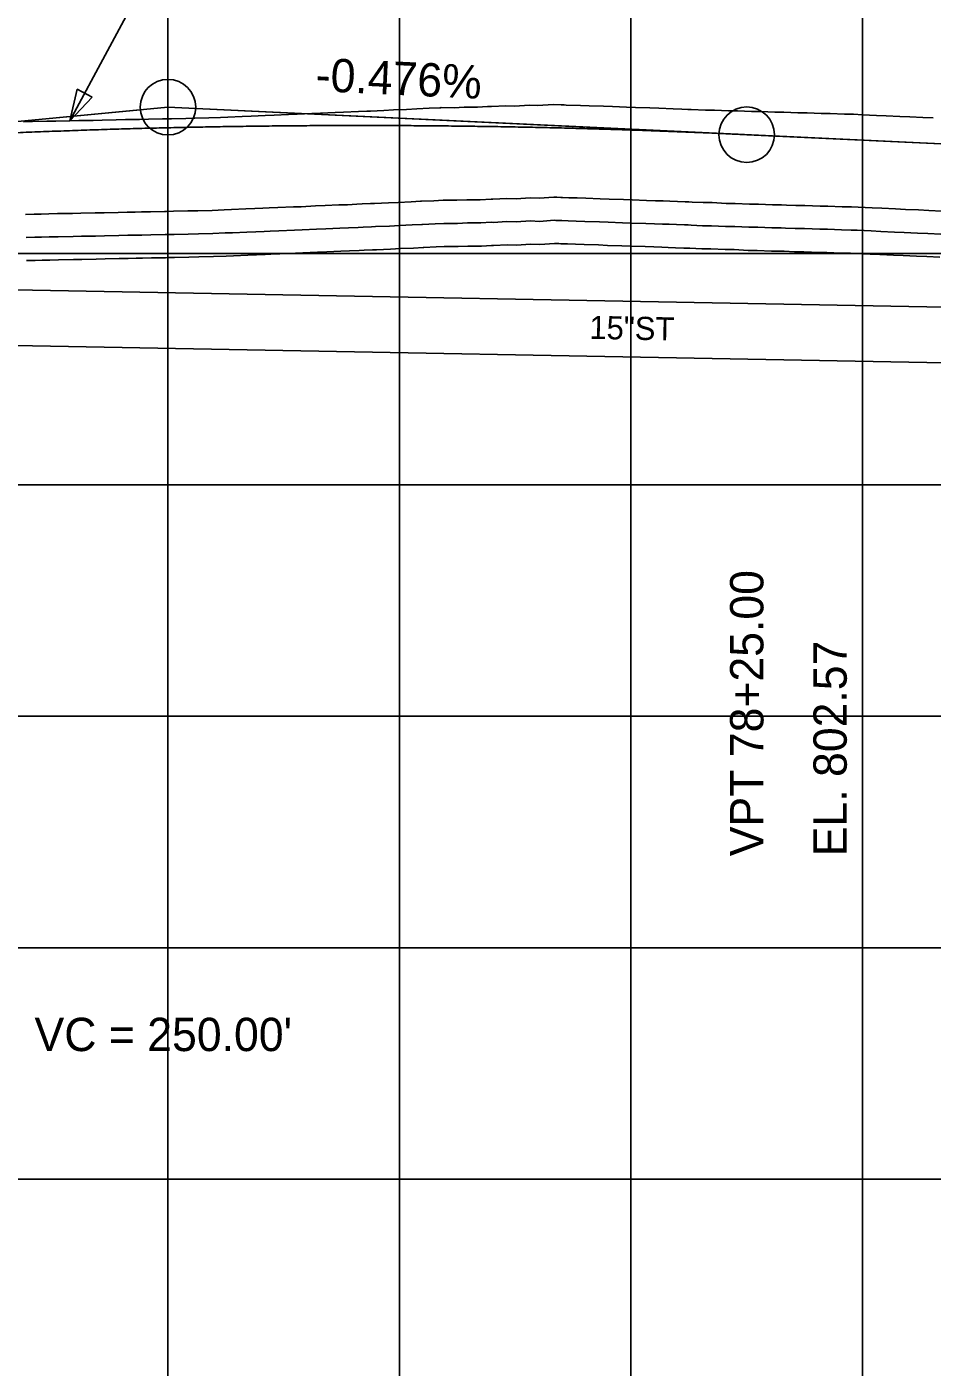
# Model space of a CAD drawing. Extents: x -7164 to 2214450, y -19642 to 253469.
# Drawn here: x 1669.5 to 1865.1, y -1740.6 to -1451 of the extents above; entities that cross this region are included whole.
import ezdxf

# ---------------------------------------------------------------- set-up
doc = ezdxf.new("R2010")
doc.units = 0
for name, color, linetype in [('DESIGN - PROFILE - Proposed', 7, 'Continuous'), ('DESIGN - PROFILE - Proposed Curve Text', 7, 'Continuous'), ('DESIGN - PROFILE - Proposed Text', 7, 'Continuous'), ('DESIGN - SHEET - Light Grid', 7, 'Continuous'), ('SURVEY - PROFILE - Drainage - Storm Sewer', 7, 'Continuous'), ('SURVEY - PROFILE - Drainage - Storm Sewer Text', 7, 'Continuous'), ('SURVEY - PROFILE - Ground Line with Text', 7, 'Continuous'), ('SURVEY - PROFILE - Utilities - Cable with Text', 7, 'Continuous'), ('SURVEY - PROFILE - Utilities - Electric with Text', 7, 'Continuous'), ('XTREE', 7, 'Continuous')]:
    doc.layers.add(name, color=color, linetype=linetype)

msp = doc.modelspace()

# ---------------------------------------------------------------- linework, layer by layer
at = {"layer": 'DESIGN - PROFILE - Proposed'}
msp.add_line((1825, -1474.33), (1885.96, -1477.23), dxfattribs=at)
msp.add_line((1825, -1474.33), (1885.96, -1477.23), dxfattribs=at)
msp.add_spline([(1575, -1480.23), (1580, -1479.77), (1585, -1479.31), (1590, -1478.88), (1595, -1478.45), (1600, -1478.04), (1605, -1477.64), (1610, -1477.26), (1615, -1476.9), (1620, -1476.54), (1625, -1476.2), (1630, -1475.88), (1635, -1475.57), (1640, -1475.27), (1645, -1474.99), (1650, -1474.72), (1655, -1474.47), (1660, -1474.23), (1665, -1474.01), (1670, -1473.79), (1675, -1473.6), (1680, -1473.42), (1685, -1473.25), (1690, -1473.09), (1695, -1472.95), (1700, -1472.83), (1705, -1472.72), (1710, -1472.62), (1715, -1472.54), (1720, -1472.47), (1725, -1472.42), (1730, -1472.38), (1735, -1472.35), (1740, -1472.34), (1745, -1472.34), (1750, -1472.36), (1755, -1472.39), (1760, -1472.44), (1765, -1472.5), (1770, -1472.57), (1775, -1472.66), (1780, -1472.76), (1785, -1472.88), (1790, -1473.01), (1795, -1473.16), (1800, -1473.32), (1805, -1473.49), (1810, -1473.68), (1815, -1473.88), (1820, -1474.1), (1825, -1474.33)], degree=3, dxfattribs=at)
msp.add_spline([(1575, -1480.23), (1580, -1479.77), (1585, -1479.31), (1590, -1478.88), (1595, -1478.45), (1600, -1478.04), (1605, -1477.64), (1610, -1477.26), (1615, -1476.9), (1620, -1476.54), (1625, -1476.2), (1630, -1475.88), (1635, -1475.57), (1640, -1475.27), (1645, -1474.99), (1650, -1474.72), (1655, -1474.47), (1660, -1474.23), (1665, -1474.01), (1670, -1473.79), (1675, -1473.6), (1680, -1473.42), (1685, -1473.25), (1690, -1473.09), (1695, -1472.95), (1700, -1472.83), (1705, -1472.72), (1710, -1472.62), (1715, -1472.54), (1720, -1472.47), (1725, -1472.42), (1730, -1472.38), (1735, -1472.35), (1740, -1472.34), (1745, -1472.34), (1750, -1472.36), (1755, -1472.39), (1760, -1472.44), (1765, -1472.5), (1770, -1472.57), (1775, -1472.66), (1780, -1472.76), (1785, -1472.88), (1790, -1473.01), (1795, -1473.16), (1800, -1473.32), (1805, -1473.49), (1810, -1473.68), (1815, -1473.88), (1820, -1474.1), (1825, -1474.33)], degree=3, dxfattribs=at)
at = {"layer": 'DESIGN - PROFILE - Proposed Text'}
for p, q in [((1575, -1480.23), (1694.03, -1468.94)), ((1575, -1480.23), (1694.03, -1468.94)), ((1825, -1474.33), (1705.99, -1468.66)), ((1825, -1474.33), (1705.99, -1468.66))]:
    msp.add_line(p, q, dxfattribs=at)
msp.add_lwpolyline([(1712.38, -1425.88), (1703.2, -1425.88), (1678.83, -1471.33)], dxfattribs=at)
msp.add_lwpolyline([(1712.38, -1425.88), (1703.2, -1425.88), (1678.83, -1471.33)], dxfattribs=at)
msp.add_lwpolyline([(1683.62, -1466.23), (1678.83, -1471.33), (1680.43, -1464.52)], close=True, dxfattribs=at)
msp.add_lwpolyline([(1683.62, -1466.23), (1678.83, -1471.33), (1680.43, -1464.52)], close=True, dxfattribs=at)
for centre in [(1700, -1468.38), (1700, -1468.38), (1825, -1474.33), (1825, -1474.33)]:
    msp.add_circle(centre, 6, dxfattribs=at)
at = {"layer": 'DESIGN - SHEET - Light Grid'}
for p, q in [((1700, -3000), (1700, -1000)), ((1700, -3000), (1700, -1000)), ((1750, -3000), (1750, -1000)), ((1750, -3000), (1750, -1000)), ((1800, -3000), (1800, -1000)), ((1800, -3000), (1800, -1000)), ((1850, -3000), (1850, -1000)), ((1850, -3000), (1850, -1000)), ((0, -1500), (12400, -1500)), ((0, -1500), (12400, -1500)), ((0, -1550), (12400, -1550)), ((0, -1550), (12400, -1550)), ((0, -1600), (12400, -1600)), ((0, -1600), (12400, -1600)), ((0, -1650), (12400, -1650)), ((0, -1650), (12400, -1650)), ((0, -1700), (12400, -1700)), ((0, -1700), (12400, -1700))]:
    msp.add_line(p, q, dxfattribs=at)
at = {"layer": 'SURVEY - PROFILE - Drainage - Storm Sewer'}
for p, q in [((1504.24, -1504.8), (2097.49, -1515.9)), ((1504.24, -1504.8), (2097.49, -1515.9)), ((1504.24, -1516.8), (2097.49, -1527.9)), ((1504.24, -1516.8), (2097.49, -1527.9))]:
    msp.add_line(p, q, dxfattribs=at)
at = {"layer": 'SURVEY - PROFILE - Ground Line with Text'}
for points in [[(1668.83, -1471.54), (1670.74, -1471.5), (1673.83, -1471.44), (1675.77, -1471.4), (1678.83, -1471.33), (1680.79, -1471.29), (1683.83, -1471.23), (1685.81, -1471.19), (1688.83, -1471.12), (1690.81, -1471.08), (1693.83, -1471.02), (1695.81, -1470.97), (1698.83, -1470.91), (1700.8, -1470.87), (1703.83, -1470.8), (1705.78, -1470.76), (1708.83, -1470.69), (1711.33, -1470.58), (1712.94, -1470.52), (1716.01, -1470.38), (1717.94, -1470.32), (1721.01, -1470.17), (1722.94, -1470.11), (1726.02, -1469.96), (1727.94, -1469.9), (1731.05, -1469.75), (1732.94, -1469.68), (1736.08, -1469.53), (1737.94, -1469.47), (1741.12, -1469.32), (1742.94, -1469.25), (1743.43, -1469.24), (1743.73, -1469.22), (1746.6, -1469.11), (1748.73, -1468.98), (1751.52, -1468.86), (1753.72, -1468.74), (1756.45, -1468.62), (1758.72, -1468.49), (1758.87, -1468.49), (1758.99, -1468.48), (1761.85, -1468.51), (1763.99, -1468.38), (1766.84, -1468.4), (1768.99, -1468.27), (1769.53, -1468.24), (1769.91, -1468.25), (1772.95, -1468.06), (1774.91, -1468.15), (1778.04, -1467.93), (1779.9, -1468.03), (1783.17, -1467.77), (1784.9, -1467.88), (1785.58, -1467.9), (1785.99, -1467.92), (1789.09, -1468.01), (1790.99, -1468.1), (1794.07, -1468.19)], [(1668.83, -1471.54), (1670.74, -1471.5), (1673.83, -1471.44), (1675.77, -1471.4), (1678.83, -1471.33), (1680.79, -1471.29), (1683.83, -1471.23), (1685.81, -1471.19), (1688.83, -1471.12), (1690.81, -1471.08), (1693.83, -1471.02), (1695.81, -1470.97), (1698.83, -1470.91), (1700.8, -1470.87), (1703.83, -1470.8), (1705.78, -1470.76), (1708.83, -1470.69), (1711.33, -1470.58), (1712.94, -1470.52), (1716.01, -1470.38), (1717.94, -1470.32), (1721.01, -1470.17), (1722.94, -1470.11), (1726.02, -1469.96), (1727.94, -1469.9), (1731.05, -1469.75), (1732.94, -1469.68), (1736.08, -1469.53), (1737.94, -1469.47), (1741.12, -1469.32), (1742.94, -1469.25), (1743.43, -1469.24), (1743.73, -1469.22), (1746.6, -1469.11), (1748.73, -1468.98), (1751.52, -1468.86), (1753.72, -1468.74), (1756.45, -1468.62), (1758.72, -1468.49), (1758.87, -1468.49), (1758.99, -1468.48), (1761.85, -1468.51), (1763.99, -1468.38), (1766.84, -1468.4), (1768.99, -1468.27), (1769.53, -1468.24), (1769.91, -1468.25), (1772.95, -1468.06), (1774.91, -1468.15), (1778.04, -1467.93), (1779.9, -1468.03), (1783.17, -1467.77), (1784.9, -1467.88), (1785.58, -1467.9), (1785.99, -1467.92), (1789.09, -1468.01), (1790.99, -1468.1), (1794.07, -1468.19)], [(1794.07, -1468.19), (1795.99, -1468.27), (1799.06, -1468.37), (1800.99, -1468.45), (1804.07, -1468.54), (1805.99, -1468.62), (1809.08, -1468.71), (1810.99, -1468.79), (1812.25, -1468.85), (1813.03, -1468.85), (1816.09, -1469.01), (1818.03, -1469.02), (1821.07, -1469.17), (1823.03, -1469.17), (1826.05, -1469.33), (1828.03, -1469.33), (1831.05, -1469.48), (1833.03, -1469.48), (1836.05, -1469.63), (1838.03, -1469.63), (1841.06, -1469.77), (1843.03, -1469.77), (1846.08, -1469.92), (1848.03, -1469.92), (1850.01, -1470.01), (1853.03, -1470.16), (1855.1, -1470.25), (1858.03, -1470.39), (1860.19, -1470.48), (1863.03, -1470.62), (1865.26, -1470.71)], [(1794.07, -1468.19), (1795.99, -1468.27), (1799.06, -1468.37), (1800.99, -1468.45), (1804.07, -1468.54), (1805.99, -1468.62), (1809.08, -1468.71), (1810.99, -1468.79), (1812.25, -1468.85), (1813.03, -1468.85), (1816.09, -1469.01), (1818.03, -1469.02), (1821.07, -1469.17), (1823.03, -1469.17), (1826.05, -1469.33), (1828.03, -1469.33), (1831.05, -1469.48), (1833.03, -1469.48), (1836.05, -1469.63), (1838.03, -1469.63), (1841.06, -1469.77), (1843.03, -1469.77), (1846.08, -1469.92), (1848.03, -1469.92), (1850.01, -1470.01), (1853.03, -1470.16), (1855.1, -1470.25), (1858.03, -1470.39), (1860.19, -1470.48), (1863.03, -1470.62), (1865.26, -1470.71)]]:
    msp.add_lwpolyline(points, dxfattribs=at)
at = {"layer": 'SURVEY - PROFILE - Utilities - Cable with Text'}
msp.add_lwpolyline([(1669.46, -1501.53), (1671.34, -1501.49), (1672.81, -1501.46), (1674.47, -1501.43), (1676.38, -1501.39), (1679.61, -1501.32), (1681.41, -1501.28), (1684.47, -1501.22), (1686.43, -1501.18), (1689.48, -1501.11), (1691.43, -1501.07), (1693.12, -1501.04), (1694.48, -1501.01), (1696.43, -1500.96), (1699.48, -1500.9), (1699.95, -1500.89), (1701.42, -1500.86), (1704.48, -1500.79), (1706.68, -1500.74), (1709.86, -1500.68), (1712.56, -1500.55), (1714.15, -1500.5), (1717.24, -1500.35), (1719.15, -1500.29), (1720.98, -1500.2), (1722.25, -1500.14), (1724.14, -1500.08), (1727.52, -1499.92), (1729.16, -1499.87), (1732.31, -1499.72), (1734.33, -1499.65), (1737.34, -1499.5), (1739.18, -1499.44), (1741.31, -1499.34), (1742.39, -1499.29), (1744.16, -1499.23), (1745.01, -1499.19), (1748.1, -1499.07), (1750.24, -1498.94), (1753.03, -1498.82), (1755.15, -1498.7), (1755.25, -1498.69), (1757.92, -1498.58), (1759.67, -1498.49), (1759.9, -1498.49), (1762.66, -1498.51), (1764.79, -1498.38), (1767.73, -1498.4), (1769.9, -1498.27), (1770.3, -1498.28), (1773.25, -1498.1), (1775.3, -1498.19), (1778.33, -1497.98), (1780.32, -1498.08), (1783.45, -1497.84), (1783.51, -1497.84), (1784.45, -1497.87), (1784.85, -1497.89), (1786.29, -1497.93), (1788, -1497.99), (1789.88, -1498.07), (1793, -1498.16), (1794.9, -1498.25), (1798, -1498.34), (1799.92, -1498.42), (1803.03, -1498.51), (1804.93, -1498.59), (1806.66, -1498.64), (1808.06, -1498.68), (1809.59, -1498.74), (1811.43, -1498.84), (1812.21, -1498.84), (1812.72, -1498.87), (1815.32, -1499), (1817.24, -1499.01), (1820.31, -1499.17), (1822.27, -1499.17), (1825.32, -1499.32), (1827.28, -1499.32), (1830.33, -1499.47), (1832.29, -1499.47), (1833.09, -1499.51), (1835.34, -1499.62), (1837.36, -1499.62), (1840.66, -1499.77), (1842.3, -1499.77), (1845.35, -1499.92), (1847.43, -1499.93), (1848.62, -1499.98), (1851.67, -1500.12), (1853.72, -1500.21), (1856.67, -1500.35), (1858.81, -1500.45), (1861.67, -1500.58), (1863.88, -1500.68), (1866.68, -1500.81)], dxfattribs=at)
msp.add_lwpolyline([(1669.46, -1501.53), (1671.34, -1501.49), (1672.81, -1501.46), (1674.47, -1501.43), (1676.38, -1501.39), (1679.61, -1501.32), (1681.41, -1501.28), (1684.47, -1501.22), (1686.43, -1501.18), (1689.48, -1501.11), (1691.43, -1501.07), (1693.12, -1501.04), (1694.48, -1501.01), (1696.43, -1500.96), (1699.48, -1500.9), (1699.95, -1500.89), (1701.42, -1500.86), (1704.48, -1500.79), (1706.68, -1500.74), (1709.86, -1500.68), (1712.56, -1500.55), (1714.15, -1500.5), (1717.24, -1500.35), (1719.15, -1500.29), (1720.98, -1500.2), (1722.25, -1500.14), (1724.14, -1500.08), (1727.52, -1499.92), (1729.16, -1499.87), (1732.31, -1499.72), (1734.33, -1499.65), (1737.34, -1499.5), (1739.18, -1499.44), (1741.31, -1499.34), (1742.39, -1499.29), (1744.16, -1499.23), (1745.01, -1499.19), (1748.1, -1499.07), (1750.24, -1498.94), (1753.03, -1498.82), (1755.15, -1498.7), (1755.25, -1498.69), (1757.92, -1498.58), (1759.67, -1498.49), (1759.9, -1498.49), (1762.66, -1498.51), (1764.79, -1498.38), (1767.73, -1498.4), (1769.9, -1498.27), (1770.3, -1498.28), (1773.25, -1498.1), (1775.3, -1498.19), (1778.33, -1497.98), (1780.32, -1498.08), (1783.45, -1497.84), (1783.51, -1497.84), (1784.45, -1497.87), (1784.85, -1497.89), (1786.29, -1497.93), (1788, -1497.99), (1789.88, -1498.07), (1793, -1498.16), (1794.9, -1498.25), (1798, -1498.34), (1799.92, -1498.42), (1803.03, -1498.51), (1804.93, -1498.59), (1806.66, -1498.64), (1808.06, -1498.68), (1809.59, -1498.74), (1811.43, -1498.84), (1812.21, -1498.84), (1812.72, -1498.87), (1815.32, -1499), (1817.24, -1499.01), (1820.31, -1499.17), (1822.27, -1499.17), (1825.32, -1499.32), (1827.28, -1499.32), (1830.33, -1499.47), (1832.29, -1499.47), (1833.09, -1499.51), (1835.34, -1499.62), (1837.36, -1499.62), (1840.66, -1499.77), (1842.3, -1499.77), (1845.35, -1499.92), (1847.43, -1499.93), (1848.62, -1499.98), (1851.67, -1500.12), (1853.72, -1500.21), (1856.67, -1500.35), (1858.81, -1500.45), (1861.67, -1500.58), (1863.88, -1500.68), (1866.68, -1500.81)], dxfattribs=at)
at = {"layer": 'SURVEY - PROFILE - Utilities - Electric with Text'}
for points in [[(1669.25, -1491.54), (1671.13, -1491.5), (1672.61, -1491.47), (1674.26, -1491.43), (1676.17, -1491.39), (1679.4, -1491.33), (1681.19, -1491.29), (1684.26, -1491.22), (1686.21, -1491.18), (1689.26, -1491.12), (1691.22, -1491.07), (1692.92, -1491.04), (1694.27, -1491.01), (1696.22, -1490.97), (1699.27, -1490.9), (1699.72, -1490.89), (1701.21, -1490.86), (1704.27, -1490.8), (1706.47, -1490.75), (1709.52, -1490.68), (1712.16, -1490.56), (1713.75, -1490.51), (1716.84, -1490.36), (1718.75, -1490.3), (1720.51, -1490.21), (1721.85, -1490.15), (1723.74, -1490.09), (1727.13, -1489.93), (1728.76, -1489.88), (1731.9, -1489.73), (1733.92, -1489.66), (1736.93, -1489.51), (1738.77, -1489.45), (1740.83, -1489.35), (1741.98, -1489.3), (1743.76, -1489.23), (1744.59, -1489.2), (1747.61, -1489.08), (1749.74, -1488.95), (1752.53, -1488.84), (1754.57, -1488.72), (1754.74, -1488.71), (1757.44, -1488.59), (1759.44, -1488.48), (1759.98, -1488.49), (1762.39, -1488.51), (1764.52, -1488.38), (1767.46, -1488.4), (1769.78, -1488.26), (1770.17, -1488.27), (1773.16, -1488.09), (1775.17, -1488.18), (1778.24, -1487.96), (1780.18, -1488.06), (1783.37, -1487.81), (1783.97, -1487.85), (1784.83, -1487.88), (1785.24, -1487.9), (1786.6, -1487.94), (1788.38, -1487.99), (1790.25, -1488.07), (1793.36, -1488.17), (1795.27, -1488.25), (1798.37, -1488.34), (1800.28, -1488.43), (1803.38, -1488.52), (1805.28, -1488.6), (1806.94, -1488.65), (1808.41, -1488.69), (1810.06, -1488.75), (1811.71, -1488.84), (1812.48, -1488.84), (1813.24, -1488.88), (1815.59, -1489), (1817.51, -1489.01), (1820.57, -1489.17), (1822.53, -1489.17), (1825.57, -1489.32), (1827.53, -1489.32), (1830.58, -1489.47), (1832.54, -1489.47), (1833.58, -1489.52), (1835.59, -1489.62), (1837.58, -1489.62), (1840.89, -1489.77), (1842.55, -1489.77), (1845.6, -1489.92), (1847.66, -1489.93), (1849.08, -1489.99), (1852.12, -1490.13), (1854.18, -1490.22), (1857.13, -1490.36), (1859.26, -1490.46), (1862.13, -1490.59), (1864.34, -1490.69), (1867.13, -1490.82)], [(1669.25, -1491.54), (1671.13, -1491.5), (1672.61, -1491.47), (1674.26, -1491.43), (1676.17, -1491.39), (1679.4, -1491.33), (1681.19, -1491.29), (1684.26, -1491.22), (1686.21, -1491.18), (1689.26, -1491.12), (1691.22, -1491.07), (1692.92, -1491.04), (1694.27, -1491.01), (1696.22, -1490.97), (1699.27, -1490.9), (1699.72, -1490.89), (1701.21, -1490.86), (1704.27, -1490.8), (1706.47, -1490.75), (1709.52, -1490.68), (1712.16, -1490.56), (1713.75, -1490.51), (1716.84, -1490.36), (1718.75, -1490.3), (1720.51, -1490.21), (1721.85, -1490.15), (1723.74, -1490.09), (1727.13, -1489.93), (1728.76, -1489.88), (1731.9, -1489.73), (1733.92, -1489.66), (1736.93, -1489.51), (1738.77, -1489.45), (1740.83, -1489.35), (1741.98, -1489.3), (1743.76, -1489.23), (1744.59, -1489.2), (1747.61, -1489.08), (1749.74, -1488.95), (1752.53, -1488.84), (1754.57, -1488.72), (1754.74, -1488.71), (1757.44, -1488.59), (1759.44, -1488.48), (1759.98, -1488.49), (1762.39, -1488.51), (1764.52, -1488.38), (1767.46, -1488.4), (1769.78, -1488.26), (1770.17, -1488.27), (1773.16, -1488.09), (1775.17, -1488.18), (1778.24, -1487.96), (1780.18, -1488.06), (1783.37, -1487.81), (1783.97, -1487.85), (1784.83, -1487.88), (1785.24, -1487.9), (1786.6, -1487.94), (1788.38, -1487.99), (1790.25, -1488.07), (1793.36, -1488.17), (1795.27, -1488.25), (1798.37, -1488.34), (1800.28, -1488.43), (1803.38, -1488.52), (1805.28, -1488.6), (1806.94, -1488.65), (1808.41, -1488.69), (1810.06, -1488.75), (1811.71, -1488.84), (1812.48, -1488.84), (1813.24, -1488.88), (1815.59, -1489), (1817.51, -1489.01), (1820.57, -1489.17), (1822.53, -1489.17), (1825.57, -1489.32), (1827.53, -1489.32), (1830.58, -1489.47), (1832.54, -1489.47), (1833.58, -1489.52), (1835.59, -1489.62), (1837.58, -1489.62), (1840.89, -1489.77), (1842.55, -1489.77), (1845.6, -1489.92), (1847.66, -1489.93), (1849.08, -1489.99), (1852.12, -1490.13), (1854.18, -1490.22), (1857.13, -1490.36), (1859.26, -1490.46), (1862.13, -1490.59), (1864.34, -1490.69), (1867.13, -1490.82)], [(1669.36, -1496.54), (1671.23, -1496.49), (1672.71, -1496.47), (1674.36, -1496.43), (1676.27, -1496.39), (1679.5, -1496.32), (1681.3, -1496.28), (1684.37, -1496.22), (1686.32, -1496.18), (1689.37, -1496.12), (1691.32, -1496.07), (1693.02, -1496.04), (1694.37, -1496.01), (1696.32, -1495.97), (1699.37, -1495.9), (1699.83, -1495.89), (1701.32, -1495.86), (1704.38, -1495.79), (1706.58, -1495.75), (1709.69, -1495.68), (1712.36, -1495.55), (1713.95, -1495.5), (1717.04, -1495.36), (1718.95, -1495.29), (1720.75, -1495.21), (1722.05, -1495.15), (1723.94, -1495.08), (1727.32, -1494.93), (1728.96, -1494.87), (1732.11, -1494.72), (1734.13, -1494.65), (1737.13, -1494.51), (1738.97, -1494.45), (1741.07, -1494.35), (1742.19, -1494.29), (1743.96, -1494.23), (1744.8, -1494.19), (1747.86, -1494.07), (1749.99, -1493.94), (1752.78, -1493.83), (1754.86, -1493.71), (1754.99, -1493.7), (1757.68, -1493.59), (1759.56, -1493.49), (1759.94, -1493.49), (1762.52, -1493.51), (1764.66, -1493.38), (1767.6, -1493.4), (1769.84, -1493.26), (1770.23, -1493.28), (1773.21, -1493.1), (1775.23, -1493.18), (1778.29, -1492.97), (1780.25, -1493.07), (1783.41, -1492.82), (1783.74, -1492.85), (1784.64, -1492.87), (1785.04, -1492.89), (1786.44, -1492.94), (1788.19, -1492.99), (1790.06, -1493.07), (1793.18, -1493.17), (1795.08, -1493.25), (1798.18, -1493.34), (1800.1, -1493.42), (1803.2, -1493.51), (1805.11, -1493.59), (1806.8, -1493.64), (1808.24, -1493.68), (1809.82, -1493.75), (1811.57, -1493.84), (1812.35, -1493.84), (1812.98, -1493.88), (1815.45, -1494), (1817.38, -1494.01), (1820.44, -1494.17), (1822.4, -1494.17), (1825.44, -1494.32), (1827.41, -1494.32), (1830.45, -1494.47), (1832.42, -1494.47), (1833.34, -1494.52), (1835.46, -1494.62), (1837.47, -1494.62), (1840.77, -1494.77), (1842.42, -1494.77), (1845.48, -1494.92), (1847.54, -1494.93), (1848.85, -1494.98), (1851.9, -1495.13), (1853.95, -1495.22), (1856.9, -1495.36), (1859.03, -1495.45), (1861.9, -1495.59), (1864.11, -1495.68), (1866.9, -1495.82)], [(1669.36, -1496.54), (1671.23, -1496.49), (1672.71, -1496.47), (1674.36, -1496.43), (1676.27, -1496.39), (1679.5, -1496.32), (1681.3, -1496.28), (1684.37, -1496.22), (1686.32, -1496.18), (1689.37, -1496.12), (1691.32, -1496.07), (1693.02, -1496.04), (1694.37, -1496.01), (1696.32, -1495.97), (1699.37, -1495.9), (1699.83, -1495.89), (1701.32, -1495.86), (1704.38, -1495.79), (1706.58, -1495.75), (1709.69, -1495.68), (1712.36, -1495.55), (1713.95, -1495.5), (1717.04, -1495.36), (1718.95, -1495.29), (1720.75, -1495.21), (1722.05, -1495.15), (1723.94, -1495.08), (1727.32, -1494.93), (1728.96, -1494.87), (1732.11, -1494.72), (1734.13, -1494.65), (1737.13, -1494.51), (1738.97, -1494.45), (1741.07, -1494.35), (1742.19, -1494.29), (1743.96, -1494.23), (1744.8, -1494.19), (1747.86, -1494.07), (1749.99, -1493.94), (1752.78, -1493.83), (1754.86, -1493.71), (1754.99, -1493.7), (1757.68, -1493.59), (1759.56, -1493.49), (1759.94, -1493.49), (1762.52, -1493.51), (1764.66, -1493.38), (1767.6, -1493.4), (1769.84, -1493.26), (1770.23, -1493.28), (1773.21, -1493.1), (1775.23, -1493.18), (1778.29, -1492.97), (1780.25, -1493.07), (1783.41, -1492.82), (1783.74, -1492.85), (1784.64, -1492.87), (1785.04, -1492.89), (1786.44, -1492.94), (1788.19, -1492.99), (1790.06, -1493.07), (1793.18, -1493.17), (1795.08, -1493.25), (1798.18, -1493.34), (1800.1, -1493.42), (1803.2, -1493.51), (1805.11, -1493.59), (1806.8, -1493.64), (1808.24, -1493.68), (1809.82, -1493.75), (1811.57, -1493.84), (1812.35, -1493.84), (1812.98, -1493.88), (1815.45, -1494), (1817.38, -1494.01), (1820.44, -1494.17), (1822.4, -1494.17), (1825.44, -1494.32), (1827.41, -1494.32), (1830.45, -1494.47), (1832.42, -1494.47), (1833.34, -1494.52), (1835.46, -1494.62), (1837.47, -1494.62), (1840.77, -1494.77), (1842.42, -1494.77), (1845.48, -1494.92), (1847.54, -1494.93), (1848.85, -1494.98), (1851.9, -1495.13), (1853.95, -1495.22), (1856.9, -1495.36), (1859.03, -1495.45), (1861.9, -1495.59), (1864.11, -1495.68), (1866.9, -1495.82)]]:
    msp.add_lwpolyline(points, dxfattribs=at)
at = {"layer": 'XTREE'}
for p, q in [((1461.37, -1491.01), (1700, -1468.38)), ((1461.37, -1491.01), (1700, -1468.38)), ((1700, -1468.38), (1885.96, -1477.23)), ((1700, -1468.38), (1885.96, -1477.23))]:
    msp.add_line(p, q, dxfattribs=at)

# ---------------------------------------------------------------- texts
at = {"layer": 'DESIGN - PROFILE - Proposed Curve Text'}
msp.add_text("VC = 250.00'", height=7.2, dxfattribs=at).set_placement((1671.18, -1672.34))
msp.add_text("VC = 250.00'", height=7.2, dxfattribs=at).set_placement((1671.18, -1672.34))
at = {"layer": 'DESIGN - PROFILE - Proposed Text'}
for s, rotation, p in [('-0.476%', 357.275, (1731.79, -1464.89)), ('-0.476%', 357.275, (1731.79, -1464.89)), ('VPT 78+25.00 ', 90, (1828.6, -1630.23)), ('VPT 78+25.00 ', 90, (1828.6, -1630.23)), ('EL. 802.57', 90, (1846.6, -1630.23)), ('EL. 802.57', 90, (1846.6, -1630.23))]:
    msp.add_text(s, height=7.2, rotation=rotation, dxfattribs=at).set_placement(p)
at = {"layer": 'SURVEY - PROFILE - Drainage - Storm Sewer Text'}
msp.add_text('15"ST', height=5, rotation=358.854, dxfattribs=at).set_placement((1790.97, -1518.44))
msp.add_text('15"ST', height=5, rotation=358.854, dxfattribs=at).set_placement((1790.97, -1518.44))

doc.saveas('drawing.dxf')
